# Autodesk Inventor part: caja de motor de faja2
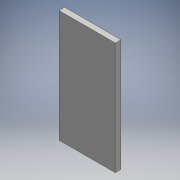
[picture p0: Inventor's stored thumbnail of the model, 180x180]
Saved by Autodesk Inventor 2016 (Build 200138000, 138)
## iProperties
Created: 2016-06
Part Number: caja de motor de faja2
Material: Genérico
Document SubType Name: Modeling
Designer: adm
Density: 1 g/cm^3
Appearance: Valor por defecto
Author: adm
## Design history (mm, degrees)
sketch "Boceto1"
  geometry: L1 (-15, -1.5)-(15, -1.5); L2 (15, -1.5)-(15, 1.5); L3 (15, 1.5)-(-15, 1.5); L4 (-15, 1.5)-(-15, -1.5); L5 (-15, -1.5)-(15, 1.5); L6 (15, -1.5)-(-15, 1.5); 1 further point
  constraints: 12 end point, 2 midpoint, 2 parallel, 1 horizontal, 1 perpendicular
  dimensions: "d0" = 30 distance of L3.end L2.end; "d1" = 3 distance of L2.end L1.end
extrude "Extrusión1" new body sketch "Boceto1" distance "d2" = 60; taper "d3" = 0 deg
node "Sólido1"
